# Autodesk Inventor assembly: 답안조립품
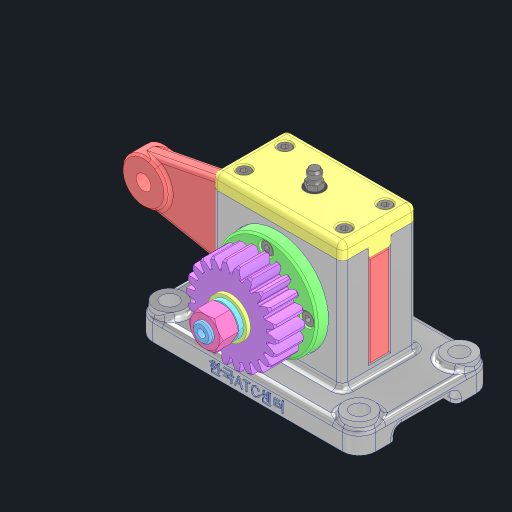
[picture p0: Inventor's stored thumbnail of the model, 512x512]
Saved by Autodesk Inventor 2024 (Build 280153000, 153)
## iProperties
Created: 2025-04
Part Number: 답안조립품
Document SubType Name: Assembly
Designer: kh_501
Author: kh_501
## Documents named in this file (15)
- C:\Users\kh_501\Desktop\750404V1007\답안조립품.iam
- C:\Users\kh_501\Desktop\750404V1007\본체.ipt
- C:\Users\kh_501\Desktop\750404V1007\그리스 니플 M6x0.75\그리스 니플 M6x0.75.ipt
- C:\Users\kh_501\Desktop\750404V1007\로드\로드.ipt
- C:\Users\kh_501\Desktop\750404V1007\스퍼기어\스퍼기어.ipt
- C:\Users\kh_501\Desktop\750404V1007\스프링와셔 M10\스프링와셔 M10.ipt
- C:\Users\kh_501\Desktop\750404V1007\실링\실링.ipt
- C:\Users\kh_501\Desktop\750404V1007\앞커버\앞커버.ipt
- C:\Users\kh_501\Desktop\750404V1007\윗커버\윗커버.ipt
- C:\Users\kh_501\Desktop\750404V1007\육각 너트 M10\육각 너트 M10.ipt
- C:\Users\kh_501\Desktop\750404V1007\육각 소켓 머리 볼트 M4x10\육각 소켓 머리 볼트 M4x10.ipt
- C:\Users\kh_501\Desktop\750404V1007\편심축\편심축.ipt
- C:\Users\kh_501\Desktop\750404V1007\평와셔 M10\평와셔 M10.ipt
- C:\Users\kh_501\Desktop\750404V1007\평행키 4x4x10\평행키 4x4x10.ipt
- C:\Users\kh_501\Desktop\750404V1007\플랜지 오일레스 부시\플랜지 오일레스 부시.ipt
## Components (3 placed, 2 different names)
1. 그리스 니플 M6x0.75:1 — 각도:5
2. 플랜지 오일레스 부시:1 — 각도:2
3. 플랜지 오일레스 부시:2 — 각도:3
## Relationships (3: Angle 3)
- 각도:2 [Angle]: 플랜지 오일레스 부시:1
- 각도:3 [Angle]: 플랜지 오일레스 부시:2
- 각도:5 [Angle]: 그리스 니플 M6x0.75:1
